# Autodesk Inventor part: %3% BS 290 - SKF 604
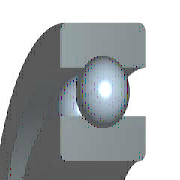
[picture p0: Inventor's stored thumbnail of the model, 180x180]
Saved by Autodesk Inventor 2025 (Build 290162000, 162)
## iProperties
Created: 2024-01
Part Number: %3% BS 290 - SKF 604
Material: Acciaio, Dolce
Description: Cuscinetti a sfere a fila singola
Document SubType Name: Modeling
Standard: BS 290
Designer: R5800u
Standards Organization: BSI
Language: it-IT
Size Designation: SKF 604
Categories: <MemberInstance><Categories><Category DisplayName="Parti albero" InternalName="7f7aeb1f-a693-4053-b835-cee3144e0d98" Mnemonic="SHFT"><Category DisplayName="Cusc
Density: 7.85 g/cm^3
Appearance: Semilucidato
IsCustomPart: 0
Author: R5800u
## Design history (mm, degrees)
node "WorkPoint1"
node "WorkAxis1"
node "WorkPlane3"
node "WorkPlane4"
node "WorkPoint2"
pattern_circular "Seriepolare1" dims "d17" = 54 (= msp_pocet), angle "d19" = 360 deg
body "Solid1"
node "Schizzo1"
revolve "Rivoluzione1" stored, may be unused: angle "d6" = 360 deg
revolve "Rivoluzione2" stored, may be unused: angle "d10" = 360 deg
node "Schizzo4"
revolve "Rivoluzione3" stored, may be unused: angle "d16" = 360 deg
fillet "Raccordo1" dims "d20" = 0.2 (= r)
sketch "Schizzo2"
  geometry: L1 (2, 4)-(6, 4); L2 (2, 0)-(2, 4); L3 (6, 0)-(2, 0); L4 (6, 4)-(6, 0); L5 (0, 0)-(0, 20); L6 (0, 0)-(0, 20); L7 (-7.2, 0)-(43.2, 0) reference
  constraints: 12 end point, 3 vertical, 2 horizontal, 1 collinear, 1 other
  dimensions: "d1" = 4 vertical distance of L1.start L5 (= Diam); "d3" = 12 diameter of L1.end L5 (= DD); "d5" = 4 distance of L2.start L1.start (= msp_mdtd2)
sketch "Schizzo3"
  geometry: L1 (4.72, 4)-(4.72, 2.96); L2 (3.28, 4)-(4.72, 4); L3 (3.28, 2.96)-(3.28, 4); L4 (3.28, 0)-(3.28, 1.04); L5 (4.72, 0)-(3.28, 0); L6 (4.72, 1.04)-(4.72, 0); L7 (6, 0)-(-6, 0) reference; L8 (6, 4)-(-6, 4) reference; L9 (0, -42.29)-(0, 61.29); L10 (0, 82.007)-(0, -63.007) reference; A1 r 1.2 centre (4, 2) between (4.72, 1.04) and (4.72, 2.96); A2 r 1.2 centre (4, 2) between (3.28, 2.96) and (3.28, 1.04)
  constraints: 14 end point, 4 collinear, 4 point on circle, 4 vertical, 2 centre point, 2 concentric, 2 horizontal, 2 point on line
  dimensions: "d9" = 2.4 diameter of A1 (= msp_mdtd6); "d21" = 3.28 distance between parallel lines of L9 L4 (= 0.5 x msp_d1); "d22" = 4 distance from line of L9 A1.centre (= 0.5 x msp_ds); "d23" = 4.72 distance between parallel lines of L9 L6 (= 0.5 x msp_dd1)
sketch "Schizzo5"
  geometry: L1 (4, 0.8)-(4, 3.2); L2 (4.72, 0)-(-4.72, 0) reference; L3 (4, 0.8)-(4, 3.2); A1 r 1.2 centre (4, 2) between (4, 0.8) and (4, 3.2); A2 r 1.2 centre (4, 2) between (4.72, 1.04) and (4.72, 2.96) reference
  constraints: 4 end point, 2 point on circle, 1 centre point, 1 concentric, 1 vertical
  dimensions: "d13" = 0 horizontal distance of A1.centre L1.start; "d15" = 2.4001 diameter of A1 (computed from msp_mdtd6)
other parameters: "Diam" = 4 [user parameter; used in 3 equation terms], "DD" = 12 [user parameter; used in 3 equation terms], "B" = 4 [user parameter; used in 1 equation term], "r" = 0.2 [user parameter; used in 1 equation term], "msp_ds" = 8 (= 0.5 x Diam + 0.5 x DD) [user parameter; used in 5 equation terms], "msp_d0" = 2.4 (= -0.3 x Diam + 0.3 x DD) [user parameter; used in 4 equation terms], "msp_d1" = 6.56 (= msp_ds - 0.6 x msp_d0) [user parameter; used in 1 equation term], "msp_dd1" = 9.44 (= msp_ds + 0.6 x msp_d0) [user parameter; used in 1 equation term], "msp_pom" = 12 (= 1.5 x msp_ds) [user parameter; used in 1 equation term], "msp_mdtd2" = 4 (= B) [user parameter; used in 3 equation terms], "msp_mdtd4" = 8 (= msp_ds) [user parameter], "msp_mdtd6" = 2.4 (= msp_d0) [user parameter; used in 2 equation terms], "msp_mdtd7" = 2 (= 0.5 x msp_mdtd2) [user parameter], "msp_pocet" = 54 (computed from msp_d0, msp_pom) [user parameter; used in 1 equation term], "d2" = 72 (derived), "d4" = 19 (derived), "d7" = 0, "d8" = 15.6 (derived), "d11" = -4 (computed from msp_mdtd2), "d12" = 0 (derived), "d14" = 15.6001 (derived), "d26" = 0, "d27" = 0, "d28" = 0, "d29" = 0, "d30" = 0
